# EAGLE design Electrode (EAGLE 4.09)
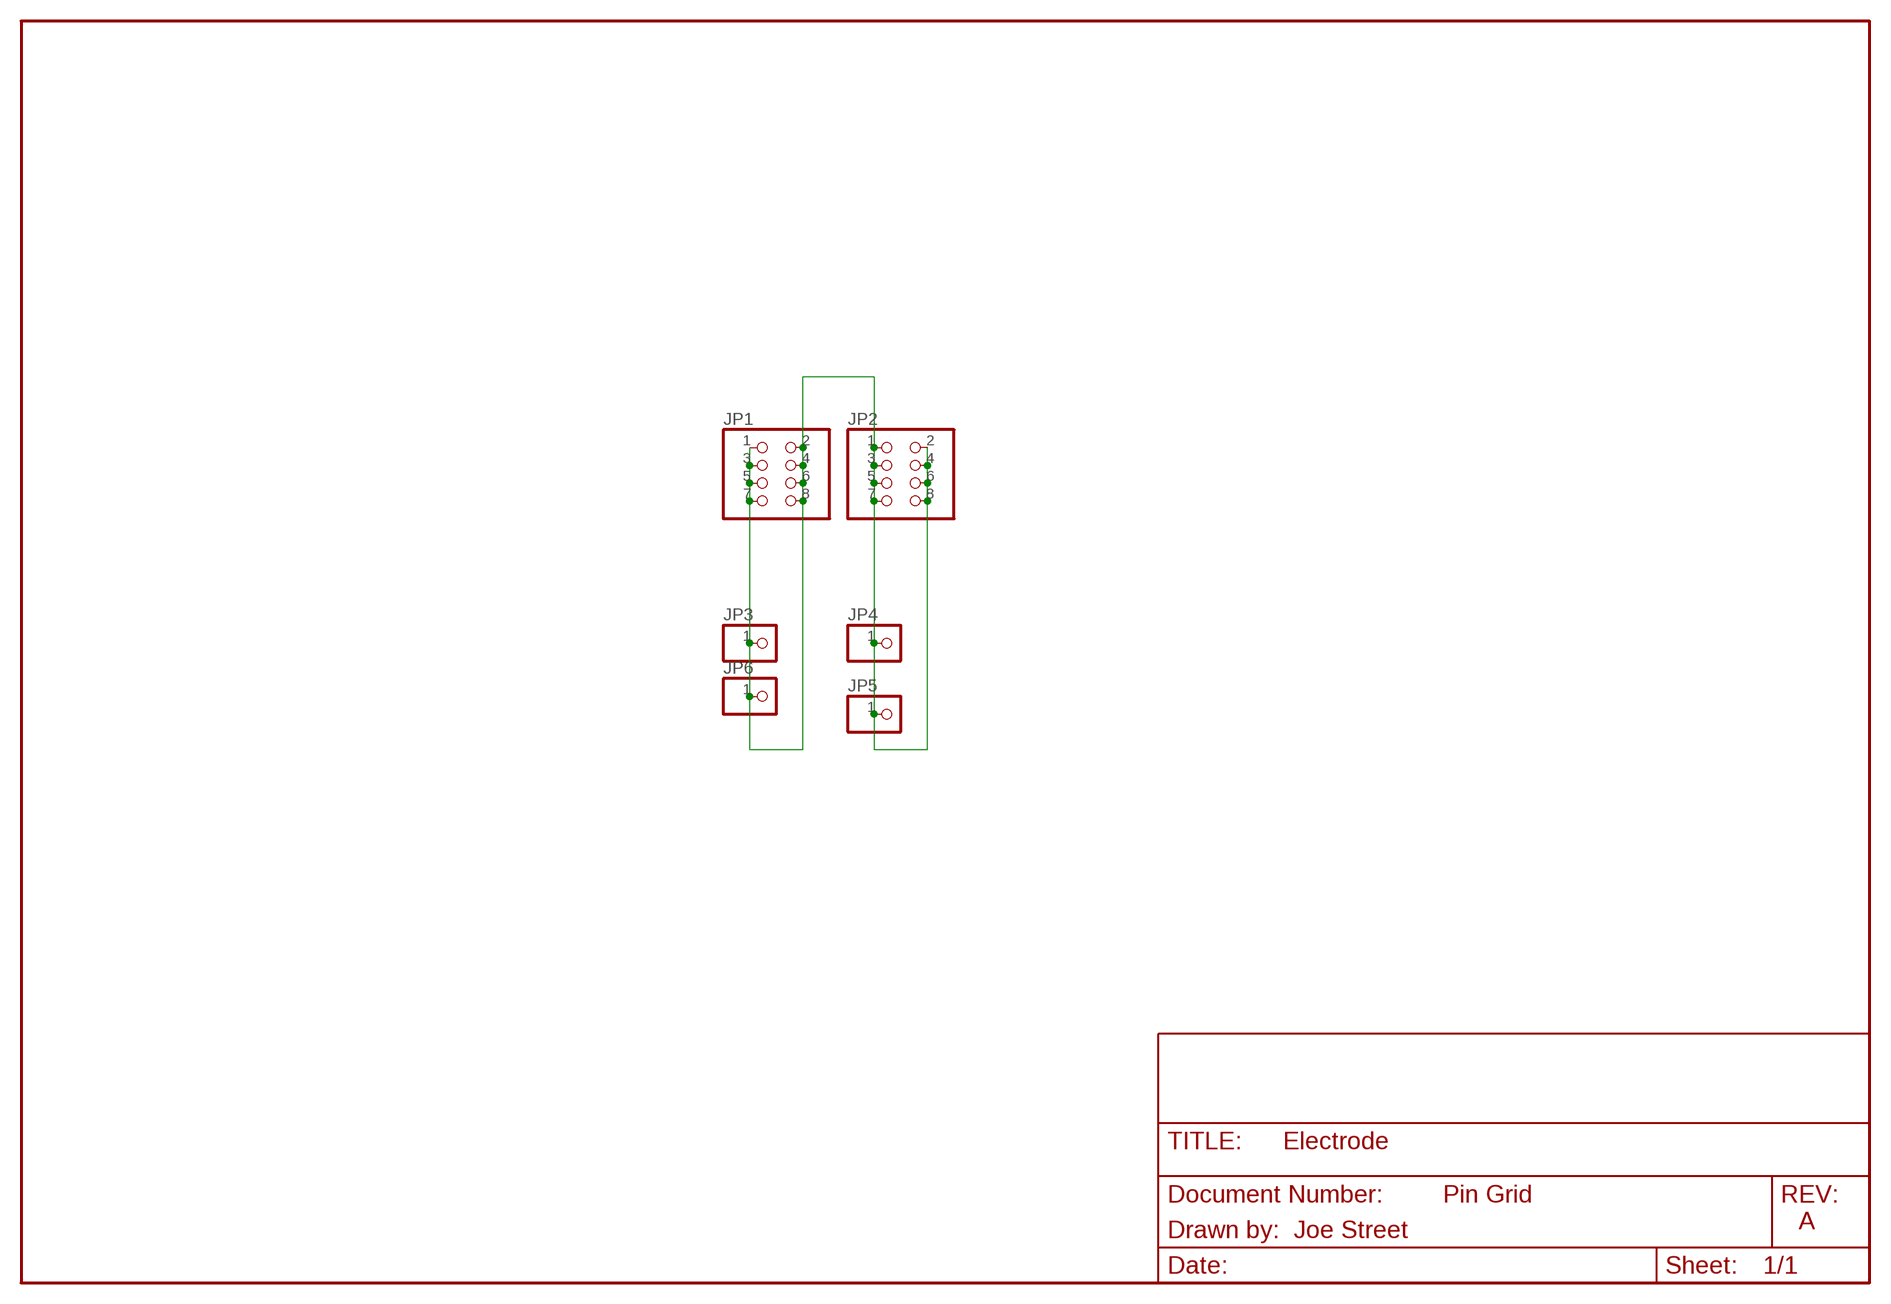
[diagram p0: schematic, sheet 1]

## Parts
JP1  PINHD-2X4  [2X04]
JP2  PINHD-2X4  [2X04]
JP3  PINHD-1X1  [1X01]
JP4  PINHD-1X1  [1X01]
JP5  PINHD-1X1  [1X01]
JP6  PINHD-1X1  [1X01]

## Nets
SIGNAL: JP1.1 JP1.2 JP1.3 JP1.4 JP1.5 JP1.6 JP1.7 JP1.8 JP2.1 JP2.2 JP2.3 JP2.4 JP2.5 JP2.6 JP2.7 JP2.8 JP3.1 JP4.1 JP5.1 JP6.1

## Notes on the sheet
- Pin Grid
- A
- Drawn by:  Joe Street

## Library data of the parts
JP1 JP2 = pc_pin:PINHD-2X4: PIN HEADER
JP3-JP6 = pinhead:PINHD-1X1: PIN HEADER

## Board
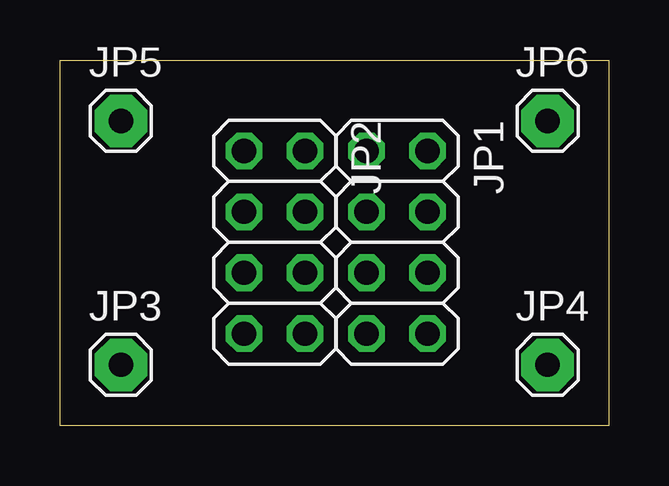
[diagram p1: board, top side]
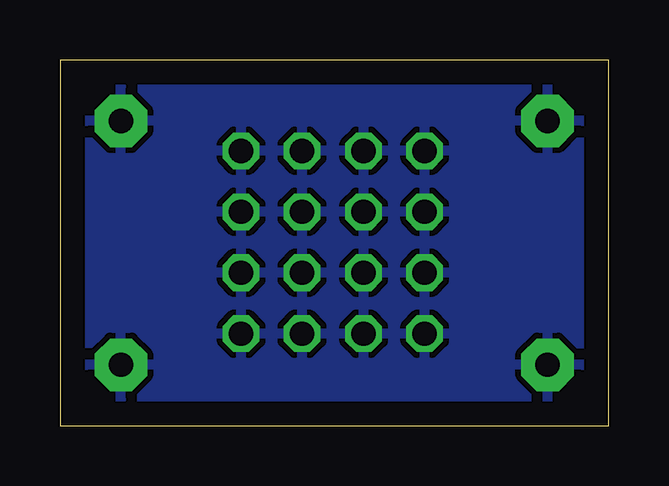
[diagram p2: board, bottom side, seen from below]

Size 22.86 x 15.24 mm. Coordinates in mm from the lower left corner, seen from the top.
Outline: 0,0 0,15.24 22.86,15.24 22.86,0 0,0
Copper layers used: Bottom

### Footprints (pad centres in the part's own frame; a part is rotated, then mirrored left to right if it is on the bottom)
2X04 = drill 1.016 octagon: 1 -3.81,-1.27; 2 -3.81,1.27; 3 -1.27,-1.27; 4 -1.27,1.27; 5 1.27,-1.27; 6 1.27,1.27; 7 3.81,-1.27; 8 3.81,1.27
1X01 = drill 1.016 pad 2.184 octagon: 1 0,0

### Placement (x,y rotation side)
JP1  14.05,7.65 270 top
JP2  8.94,7.65 270 top
JP3  2.54,2.54 0 top
JP4  20.32,2.54 0 top
JP5  2.54,12.7 0 top
JP6  20.32,12.7 0 top

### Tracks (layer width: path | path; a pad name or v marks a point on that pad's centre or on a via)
SIGNAL
  pour Bottom: 0,15.24 22.86,15.24 22.86,0 0,0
